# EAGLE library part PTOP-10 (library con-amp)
AMP connector
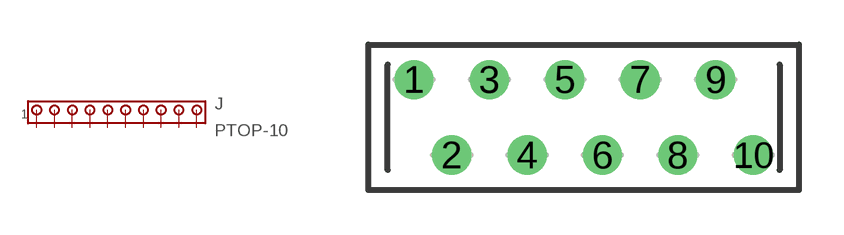
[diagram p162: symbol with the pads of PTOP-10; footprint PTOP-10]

Designator prefix J

## PTOP-10 (OC_FARNELL: unknown; OC_NEWARK: unknown)  [PTOP-10]
1  1  pas
2  2  pas
3  3  pas
4  4  pas
5  5  pas
6  6  pas
7  7  pas
8  8  pas
9  9  pas
10  10  pas

## Footprint PTOP-10 (pad centres in mm)
AMP connector
drill 0.813 round: 1 -5.715,1.27; 2 -4.445,-1.27; 3 -3.175,1.27; 4 -1.905,-1.27; 5 -0.635,1.27; 6 0.635,-1.27; 7 1.905,1.27; 8 3.175,-1.27; 9 4.445,1.27; 10 5.715,-1.27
